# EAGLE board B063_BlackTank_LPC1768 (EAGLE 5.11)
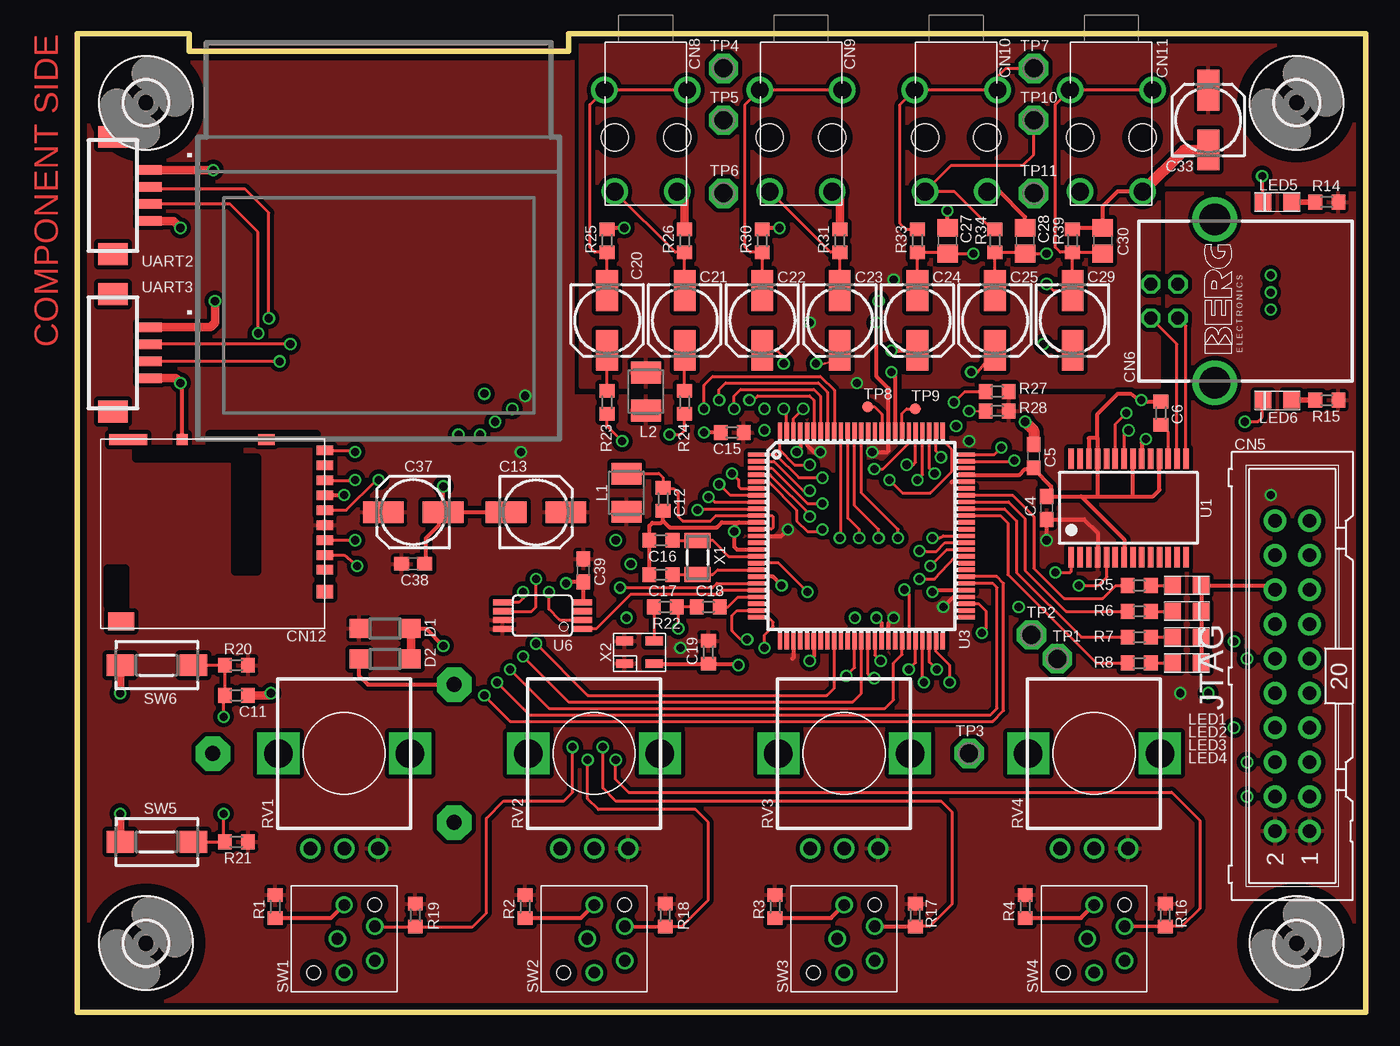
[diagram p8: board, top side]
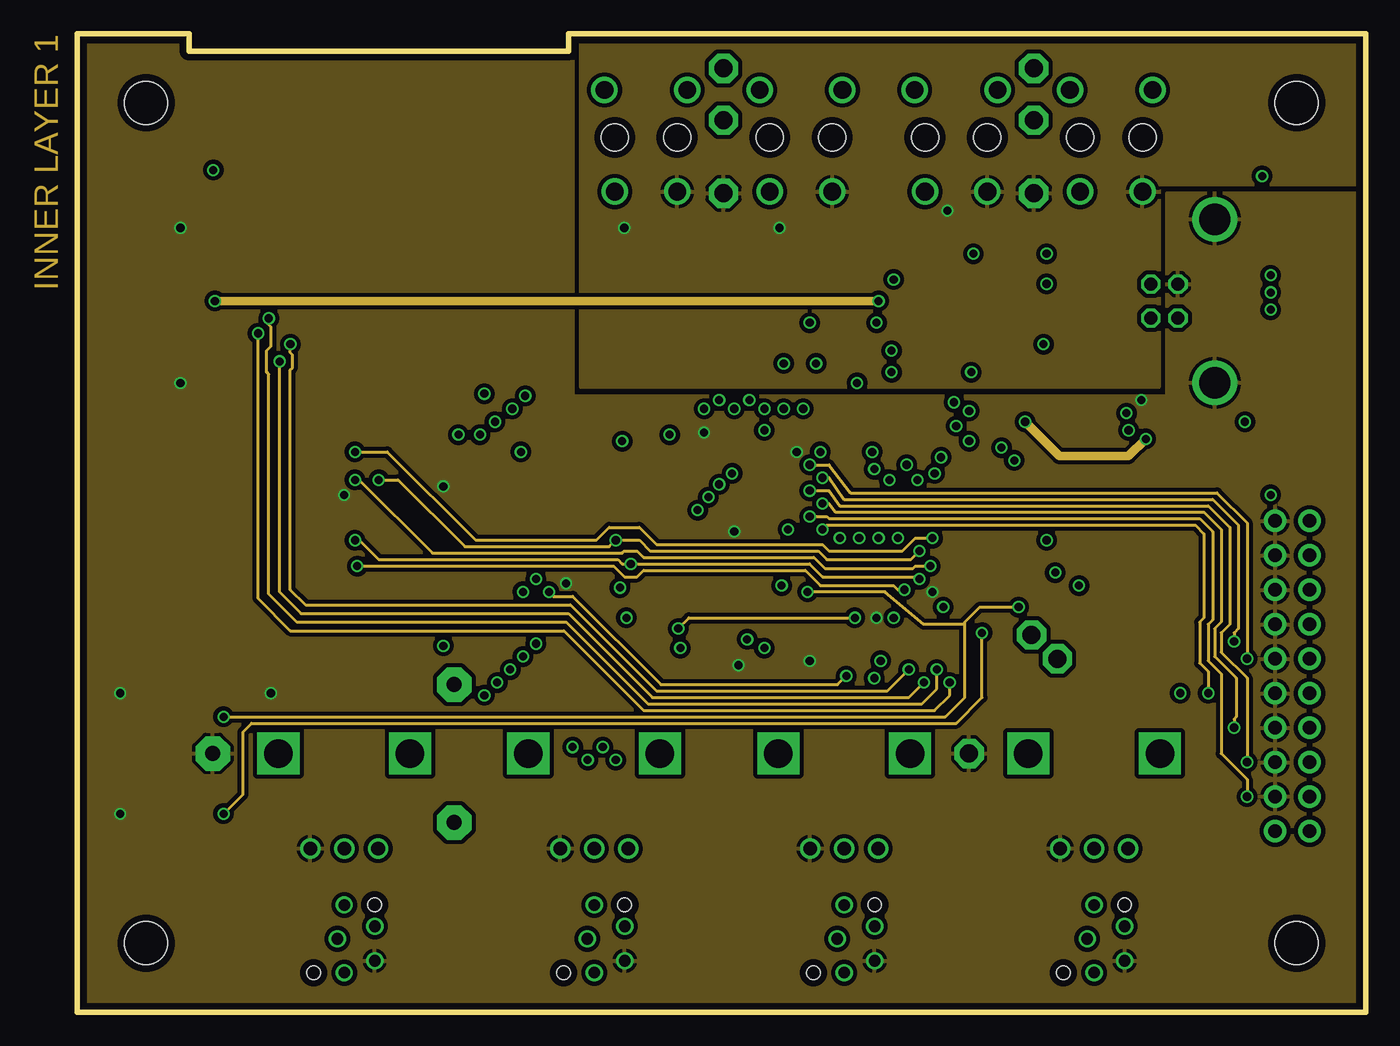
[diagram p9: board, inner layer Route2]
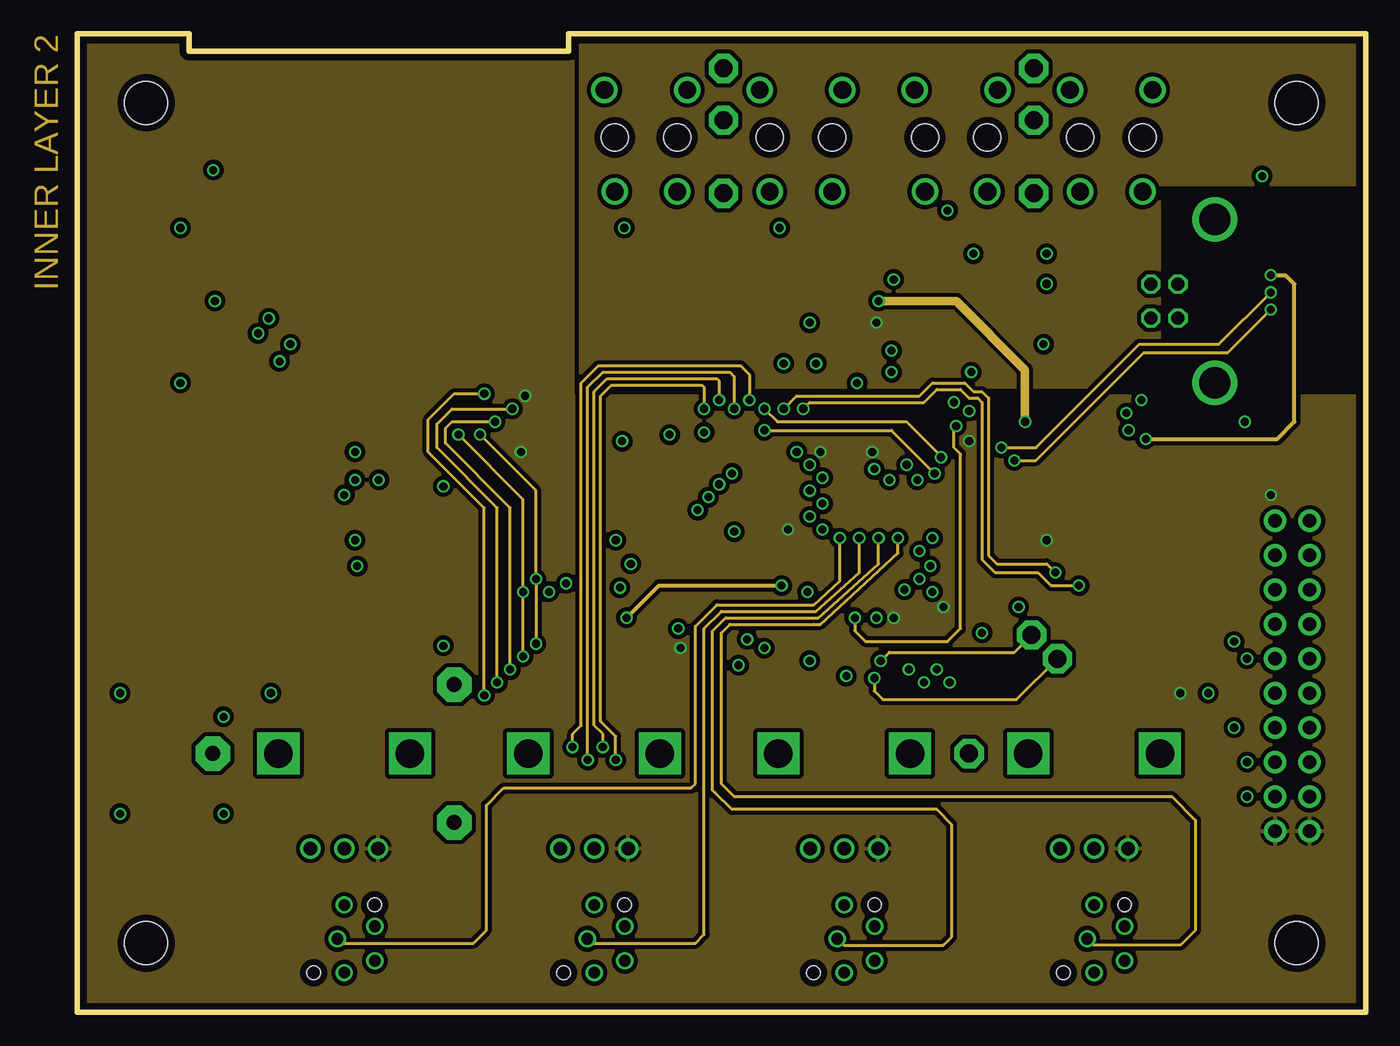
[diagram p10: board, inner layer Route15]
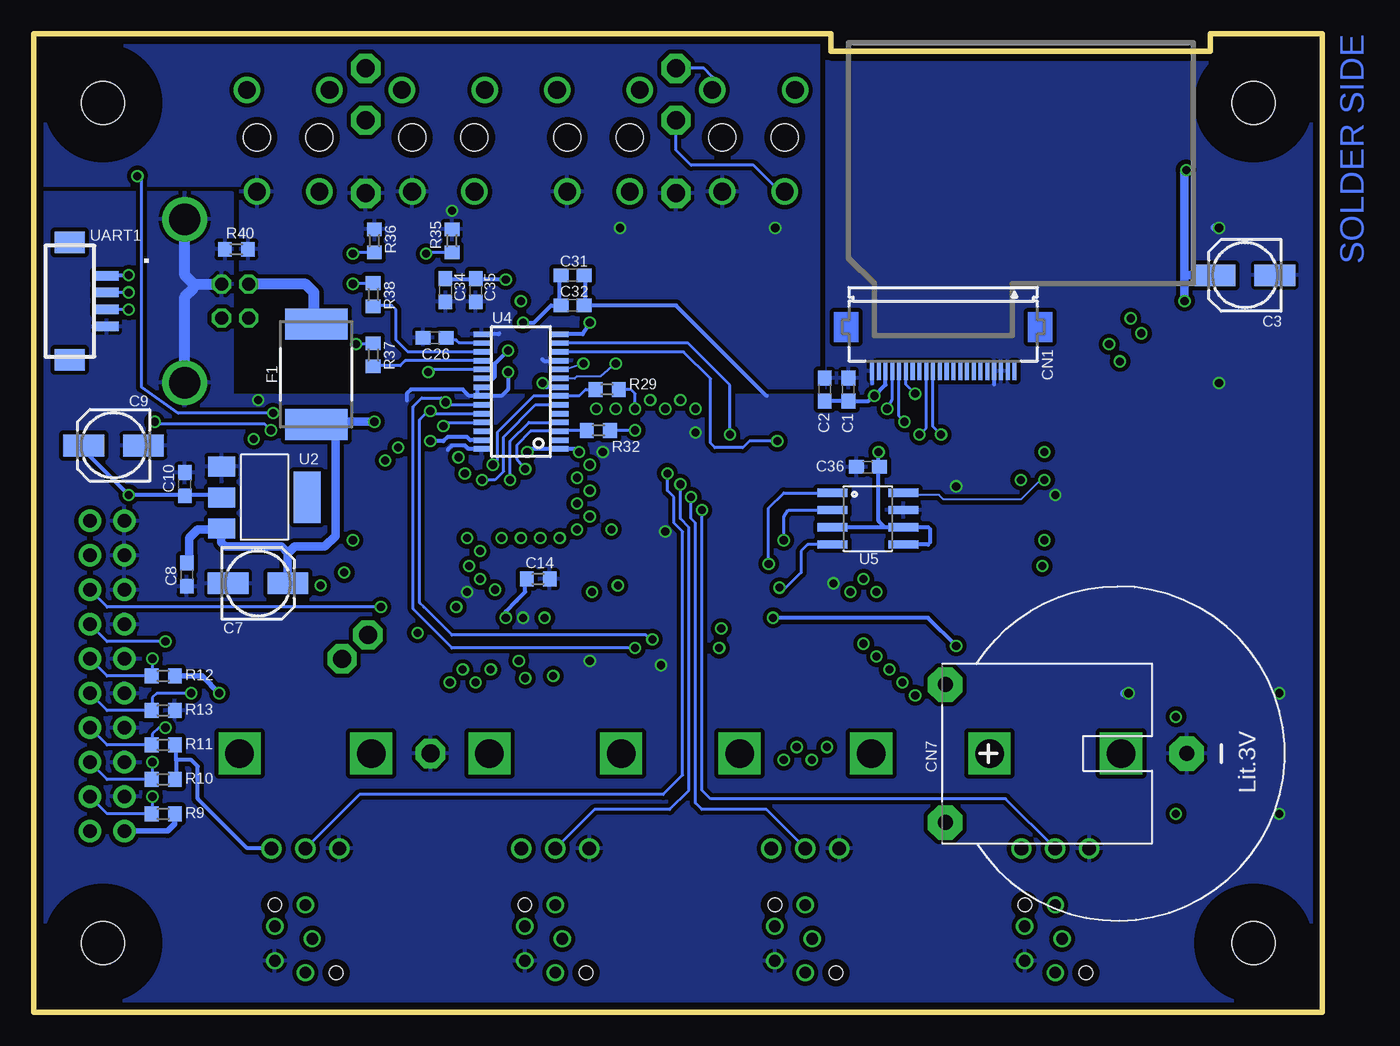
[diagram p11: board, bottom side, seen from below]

Size 94.93 x 72.07 mm. Coordinates in mm from the lower left corner, seen from the top.
Outline: 0,0 94.93,0 94.93,72.07 36.2,72.07 36.2,70.8 8.26,70.8 8.26,72.07 0,72.07 0,0
Copper layers (1+2*15+16): Top 0.018mm / dielectric 0.25mm / Route2 0.035mm / dielectric 1mm / Route15 0.035mm / dielectric 0.25mm / Bottom 0.018mm
Design rules "pban_5mil-l4 *": minimum track width 5mil, minimum drill 0.3mm, track to track 5mil, track to pad 0.229mm, pad to pad 5mil, via to via 5mil, smd to smd 5mil, copper to edge 0.5mm, drill to drill 0.5mm, minimum pad ring 0.15mm, minimum via ring 0.15mm, stop-mask expansion 4mil, vias tented up to drill 0.35mm, thermal gap 10mil
Net classes: 0 default: width 0.152 mm, drill 0.254 mm, clearance 0.152 mm; 1 PWR: width 0.305 mm, drill 0.254 mm, clearance 0.152 mm; 2 GND: width 0.305 mm, drill 0.254 mm, clearance 0.152 mm
tKeepout: area 8.9,42.1 to 35.6,70.2
bKeepout: area 8.9,51.1 to 35.6,70.2

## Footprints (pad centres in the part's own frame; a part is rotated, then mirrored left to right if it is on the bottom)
C0603 = smd 1.1 x 1: 1 -0.85,0; 2 0.85,0
153CLV-0505 = smd 3 x 1.6: + 2.2,0; - -2.2,0
0603 = smd 1 x 1.1: 1 -0.85,0; 2 0.85,0
C0805 = smd 1.3 x 1.5: 1 -0.95,0; 2 0.95,0
FH12-22S-0.5SH = smd 0.3 x 1.3: 1 -5.25,3.25; 2 -4.75,3.25; 3 -4.25,3.25; 4 -3.75,3.25; 5 -3.25,3.25; 6 -2.75,3.25; 7 -2.25,3.25; 8 -1.75,3.25; 9 -1.25,3.25; 10 -0.75,3.25; 11 -0.25,3.25; 12 0.25,3.25; 13 0.75,3.25; 14 1.25,3.25; 15 1.75,3.25; 16 2.25,3.25; 17 2.75,3.25; 18 3.25,3.25; 19 3.75,3.25; 20 4.25,3.25; 21 4.75,3.25; 22 5.25,3.25
DF13C-4P-1.25V = smd 1.6 x 2.2: M$0 4.325,-1.8; M$1 -4.325,-1.8 | smd 0.7 x 1.8: P$1 -1.875,0.9; P$2 -0.625,0.9; P$3 0.625,0.9; P$4 1.875,0.9
JTAG-20 = drill 1.016 pad 1.676 round: 1 0,0; 2 0,2.54; 3 2.54,0; 4 2.54,2.54; 5 5.08,0; 6 5.08,2.54; 7 7.62,0; 8 7.62,2.54; 9 10.16,0; 10 10.16,2.54; 11 12.7,0; 12 12.7,2.54; 13 15.24,0; 14 15.24,2.54; 15 17.78,0; 16 17.78,2.54; 17 20.32,0; 18 20.32,2.54; 19 22.86,0; 20 22.86,2.54
PN61729-S = drill 0.95 octagon: 1 1.25,4.71; 2 -1.25,4.71; 3 -1.25,2.71; 4 1.25,2.71 | drill 2.3 pad 2.9 round: S1 -6.02,0; S2 6.02,0
CR2430H = drill 1.118 pad 2.54 octagon: + 5.08,12.7; +@1 -5.08,12.7; - 0,-5.08
ST-005 = drill 1.3 round: GND -4,-2.3; L-1 3.5,3.05; L-2 3.5,-3.05; R -4,2.3 | hole 2: 0,-2.3; 0,2.3
DM3AT-SF-PEJ = smd 0.7 x 1.2: 1 2.03,7.62; 2 0.93,7.62; 3 -0.17,7.62; 4 -1.27,7.62; 5 -2.37,7.62; 6 -3.47,7.62; 7 -4.57,7.62; 8 -5.67,7.62; A -6.77,7.62 | smd 0.8 x 0.8: B -7.57,-2.88 | smd 0.8 x 1.2: PAD1 -7.57,3.32 | smd 0.8 x 2.8: PAD2 -7.57,-6.88 | smd 1.3 x 1.9: PAD3 5.83,-7.38 | smd 1 x 1.2: PAD4 3.63,7.62
SOD123 = smd 1.4 x 1.4: A 1.9,0; C -1.9,0
SMD050F = smd 2.3 x 4.6: 1 -3.7,0; 2 3.7,0
3,2 = hole 3.2: 0,0
L3230M = smd 1.6 x 2.2: 1 -1.4,0; 2 1.4,0
LED_0805 = smd 1.2 x 1.25: A 1.05,0; K -1.05,0
SK09 = drill 1 round: 1 -2.5,-7; 2 0,-7; 3 2.5,-7 | drill 2.1 square: S1 -4.85,0; S2 4.85,0
HB2 = drill 0.85 round: 1 2.25,0.92; 2 2.25,-1.62; 3 0,2.5; 4 -0.5,0; 5 0,-2.5 | hole 1: 2.25,2.5; -2.25,-2.5
DTSM-3 = smd 2 x 1.6: 1 -2.7,0; 2 2.7,0
P1-13 = drill 1.321 pad 2.159 octagon: TP 0,0
TP08R = smd 0.8 x 0.8: TP 0,0
SSOP28 = smd 0.4 x 1.5: 1 -4.225,-3.625; 2 -3.575,-3.625; 3 -2.925,-3.625; 4 -2.275,-3.625; 5 -1.625,-3.625; 6 -0.975,-3.625; 7 -0.325,-3.625; 8 0.325,-3.625; 9 0.975,-3.625; 10 1.625,-3.625; 11 2.275,-3.625; 12 2.925,-3.625; 13 3.575,-3.625; 14 4.225,-3.625; 15 4.225,3.625; 16 3.575,3.625; 17 2.925,3.625; 18 2.275,3.625; 19 1.625,3.625; 20 0.975,3.625; 21 0.325,3.625; 22 -0.325,3.625; 23 -0.975,3.625; 24 -1.625,3.625; 25 -2.275,3.625; 26 -2.925,3.625; 27 -3.575,3.625; 28 -4.225,3.625
SOT223 = smd 1.499 x 2.007: 1 -2.261,-3.15; 2 0.025,-3.15; 3 2.311,-3.15 | smd 3.81 x 2.007: 4 0,3.15
LQFP100 = smd 1.2 x 0.32: 1 -7.75,6; 2 -7.75,5.5; 3 -7.75,5; 4 -7.75,4.5; 5 -7.75,4; 6 -7.75,3.5; 7 -7.75,3; 8 -7.75,2.5; 9 -7.75,2; 10 -7.75,1.5; 11 -7.75,1; 12 -7.75,0.5; 13 -7.75,0; 14 -7.75,-0.5; 15 -7.75,-1; 16 -7.75,-1.5; 17 -7.75,-2; 18 -7.75,-2.5; 19 -7.75,-3; 20 -7.75,-3.5; 21 -7.75,-4; 22 -7.75,-4.5; 23 -7.75,-5; 24 -7.75,-5.5; 25 -7.75,-6; 51 7.75,-6; 52 7.75,-5.5; 53 7.75,-5; 54 7.75,-4.5; 55 7.75,-4; 56 7.75,-3.5; 57 7.75,-3; 58 7.75,-2.5; 59 7.75,-2; 60 7.75,-1.5; 61 7.75,-1; 62 7.75,-0.5; 63 7.75,0; 64 7.75,0.5; 65 7.75,1; 66 7.75,1.5; 67 7.75,2; 68 7.75,2.5; 69 7.75,3; 70 7.75,3.5; 71 7.75,4; 72 7.75,4.5; 73 7.75,5; 74 7.75,5.5; 75 7.75,6 | smd 0.32 x 1.2: 26 -6,-7.75; 27 -5.5,-7.75; 28 -5,-7.75; 29 -4.5,-7.75; 30 -4,-7.75; 31 -3.5,-7.75; 32 -3,-7.75; 33 -2.5,-7.75; 34 -2,-7.75; 35 -1.5,-7.75; 36 -1,-7.75; 37 -0.5,-7.75; 38 0,-7.75; 39 0.5,-7.75; 40 1,-7.75; 41 1.5,-7.75; 42 2,-7.75; 43 2.5,-7.75; 44 3,-7.75; 45 3.5,-7.75; 46 4,-7.75; 47 4.5,-7.75; 48 5,-7.75; 49 5.5,-7.75; 50 6,-7.75; 76 6,7.75; 77 5.5,7.75; 78 5,7.75; 79 4.5,7.75; 80 4,7.75; 81 3.5,7.75; 82 3,7.75; 83 2.5,7.75; 84 2,7.75; 85 1.5,7.75; 86 1,7.75; 87 0.5,7.75; 88 0,7.75; 89 -0.5,7.75; 90 -1,7.75; 91 -1.5,7.75; 92 -2,7.75; 93 -2.5,7.75; 94 -3,7.75; 95 -3.5,7.75; 96 -4,7.75; 97 -4.5,7.75; 98 -5,7.75; 99 -5.5,7.75; 100 -6,7.75
R-PDSO-G28 = smd 0.4 x 1.2: 1 -4.225,-2.9; 2 -3.575,-2.9; 3 -2.925,-2.9; 4 -2.275,-2.9; 5 -1.625,-2.9; 6 -0.975,-2.9; 7 -0.325,-2.9; 8 0.325,-2.9; 9 0.975,-2.9; 10 1.625,-2.9; 11 2.275,-2.9; 12 2.925,-2.9; 13 3.575,-2.9; 14 4.225,-2.9; 15 4.225,2.9; 16 3.575,2.9; 17 2.925,2.9; 18 2.275,2.9; 19 1.625,2.9; 20 0.975,2.9; 21 0.325,2.9; 22 -0.325,2.9; 23 -0.975,2.9; 24 -1.625,2.9; 25 -2.275,2.9; 26 -2.925,2.9; 27 -3.575,2.9; 28 -4.225,2.9
SO08 = smd 0.61 x 2.21: 1 -1.905,-2.616; 2 -0.635,-2.616; 3 0.635,-2.616; 4 1.905,-2.616; 5 1.905,2.616; 6 0.635,2.616; 7 -0.635,2.616; 8 -1.905,2.616
TSSOP8 = smd 0.45 x 1.45: 1 -0.975,-2.925; 2 -0.325,-2.925; 3 0.325,-2.925; 4 0.975,-2.925; 5 0.975,2.925; 6 0.325,2.925; 7 -0.325,2.925; 8 -0.975,2.925
FC135 = smd 1.1 x 1.9: X1 -1.25,0; X2 1.25,0
OSC3.2X.2.5 = smd 1.27 x 0.635: P$1 -1.092,-0.838; P$2 1.092,-0.838; P$3 1.092,0.838; P$4 -1.092,0.838

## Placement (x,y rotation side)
C1  0.1u  [C0603]  34.92,45.88 90 bottom
C2  0.1u  [C0603]  36.67,45.88 90 bottom
C3  10u  [153CLV-0505]  5.71,54.29 180 bottom
C4  0.1u  [C0603]  71.44,37.15 90 top
C5  0.1u  [C0603]  70.48,40.96 270 top
C6  0.1u  [0603]  79.85,44.13 270 top
C7  10u  [153CLV-0505]  78.42,31.59 0 bottom
C8  0.1u  [C0603]  83.66,32.23 270 bottom
C9  10u  [153CLV-0505]  89.06,41.75 180 bottom
C10  0.1u  [C0603]  83.82,38.89 90 bottom
C11  0.1u  [0603]  11.75,23.34 180 top
C12  0.1u  [0603]  43.18,37.78 270 top
C13  10u  [153CLV-0505]  33.81,36.83 0 top
C14  0.1u  [0603]  57.78,31.91 0 bottom
C15  0.1u  [0603]  48.26,42.7 180 top
C16  22p  [0603]  43.02,34.77 0 top
C17  22p  [0603]  43.02,32.23 0 top
C18  0.1u  [0603]  46.51,29.84 0 top
C19  0.1u  [0603]  46.51,26.51 90 top
C20  10u  [153CLV-0505]  39.05,50.96 270 top
C21  10u  [153CLV-0505]  44.77,50.96 270 top
C22  10u  [153CLV-0505]  50.48,50.96 270 top
C23  10u  [153CLV-0505]  56.2,50.96 270 top
C24  10u  [153CLV-0505]  61.91,50.96 270 top
C25  10u  [153CLV-0505]  67.63,50.96 270 top
C26  0.1u  [C0603]  65.41,49.69 180 bottom
C27  470p  [C0805]  64.14,56.83 90 top
C28  470p  [C0805]  69.85,56.83 90 top
C29  10u  [153CLV-0505]  73.34,50.96 270 top
C30  27p  [C0805]  75.56,56.83 90 top
C31  0.1u  [C0603]  55.24,54.29 0 bottom
C32  0.1u  [C0603]  55.24,52.07 0 bottom
C33  10u  [153CLV-0505]  83.34,65.72 90 top
C34  0.1u  [C0603]  64.61,53.18 270 bottom
C35  0.1u  [C0603]  62.39,53.18 270 bottom
C36  0.1u  [C0603]  33.5,40.16 180 bottom
C37  10u  [153CLV-0505]  24.77,36.83 180 top
C38  0.1u  [C0603]  24.77,33.02 0 top
C39  0.1u  [C0603]  37.31,32.54 270 top
CN1  [FH12-22S-0.5SH]  27.94,50.48 180 bottom
CN2  DF13-4P-1.25V  [DF13C-4P-1.25V]  90.49,52.39 270 bottom
CN3  [DF13C-4P-1.25V]  4.45,60.17 270 top
CN4  [DF13C-4P-1.25V]  4.45,48.58 270 top
CN5  [JTAG-20]  90.81,13.34 90 top
CN6  [PN61729-S]  83.82,52.39 90 top
CN7  CR2430H  [CR2430H]  15.08,19.05 90 bottom
CN8  [ST-005]  41.91,64.45 90 top
CN9  [ST-005]  53.34,64.45 90 top
CN10  [ST-005]  64.77,64.45 90 top
CN11  [ST-005]  76.2,64.45 90 top
CN12  [DM3AT-SF-PEJ]  10.64,34.61 270 top
D1  [SOD123]  22.7,28.26 180 top
D2  [SOD123]  22.7,26.04 180 top
F1  [SMD050F]  74.14,46.99 270 bottom
H1  [3,2]  5.08,66.99 0 top
H2  [3,2]  5.08,5.08 0 top
H3  [3,2]  89.85,5.08 0 top
H4  [3,2]  89.85,66.99 0 top
L1  22u  [L3230M]  40.48,38.26 90 top
L2  22u  [L3230M]  41.91,45.72 90 top
LED1  RED  [LED_0805]  81.76,31.43 180 top
LED2  RED  [LED_0805]  81.76,29.53 180 top
LED3  RED  [LED_0805]  81.76,27.62 180 top
LED4  RED  [LED_0805]  81.76,25.72 180 top
LED5  YELLOW  [LED_0805]  88.42,59.69 0 top
LED6  YELLOW  [LED_0805]  88.42,45.09 0 top
R1  220  [0603]  14.61,7.78 90 top
R2  220  [0603]  33.02,7.78 90 top
R3  220  [0603]  51.44,7.78 90 top
R4  220  [0603]  69.85,7.78 90 top
R5  220  [0603]  78.26,31.43 0 top
R6  220  [0603]  78.26,29.53 0 top
R7  220  [0603]  78.26,27.62 0 top
R8  220  [0603]  78.26,25.72 0 top
R9  10K  [0603]  85.41,14.61 0 bottom
R10  10K  [0603]  85.41,17.15 0 bottom
R11  10K  [0603]  85.41,19.69 0 bottom
R12  10K  [0603]  85.41,24.77 0 bottom
R13  10K  [0603]  85.41,22.23 0 bottom
R14  220  [0603]  92.08,59.69 180 top
R15  220  [0603]  92.08,45.08 180 top
R16  10K  [0603]  80.17,7.14 90 top
R17  10K  [0603]  61.75,7.14 90 top
R18  10K  [0603]  43.34,7.14 90 top
R19  10K  [0603]  24.92,7.14 90 top
R20  10K  [0603]  11.75,25.56 0 top
R21  10K  [0603]  11.75,12.54 0 top
R22  33  [0603]  43.34,29.84 180 top
R23  100  [0603]  39.05,44.93 270 top
R24  100  [0603]  44.77,44.93 270 top
R25  100K  [0603]  39.05,56.83 270 top
R26  100K  [0603]  44.77,56.83 270 top
R27  4.7K  [0603]  67.79,45.72 180 top
R28  4.7K  [0603]  67.79,44.29 180 top
R29  220  [0603]  52.7,45.88 0 bottom
R30  47K  [0603]  50.48,56.83 270 top
R31  47K  [0603]  56.2,56.83 270 top
R32  220  [0603]  53.34,42.86 0 bottom
R33  4.7K  [0603]  61.91,56.83 270 top
R34  4.7K  [0603]  67.63,56.83 270 top
R35  4.7K  [0603]  64.14,56.83 90 bottom
R36  4.7K  [0603]  69.85,56.83 90 bottom
R37  4.7K  [0603]  69.93,48.42 90 bottom
R38  10K  [0603]  69.93,52.86 90 bottom
R39  10K  [0603]  73.34,56.83 90 top
R40  0  [0603]  80.01,56.2 0 bottom
RV1  B10K  [SK09]  19.68,19.05 0 top
RV2  B10K  [SK09]  38.1,19.05 0 top
RV3  B10K  [SK09]  56.52,19.05 0 top
RV4  B10K  [SK09]  74.93,19.05 0 top
SW1  HB2-15SKP4RM  [HB2]  19.68,5.4 0 top
SW2  HB2-15SKP4RM  [HB2]  38.1,5.4 0 top
SW3  HB2-15SKP4RM  [HB2]  56.52,5.4 0 top
SW4  HB2-15SKP4RM  [HB2]  74.93,5.4 0 top
SW5  [DTSM-3]  5.87,12.54 0 top
SW6  [DTSM-3]  5.87,25.56 0 top
TP1  PTR1PAD1-13  [P1-13]  72.23,26.03 0 top
TP2  PTR1PAD1-13  [P1-13]  70.33,27.78 0 top
TP3  PTR1PAD1-13  [P1-13]  65.72,19.05 0 top
TP4  PTR1PAD1-13  [P1-13]  47.62,69.53 0 top
TP5  PTR1PAD1-13  [P1-13]  47.62,65.72 0 top
TP6  PTR1PAD1-13  [P1-13]  47.62,60.33 0 top
TP7  PTR1PAD1-13  [P1-13]  70.48,69.53 0 top
TP8  [TP08R]  58.26,44.61 270 top
TP9  [TP08R]  61.75,44.45 0 top
TP10  PTR1PAD1-13  [P1-13]  70.48,65.72 0 top
TP11  PTR1PAD1-13  [P1-13]  70.48,60.32 0 top
U1  [SSOP28]  77.47,37.15 0 top
U2  [SOT223]  77.95,37.94 270 bottom
U3  [LQFP100]  57.79,35.08 0 top
U4  [R-PDSO-G28]  59.05,45.72 90 bottom
U5  [SO08]  33.5,36.35 270 bottom
U6  23K256  [TSSOP8]  34.29,29.21 90 top
X1  32.768  [FC135]  45.72,33.5 90 top
X2  12.288  [OSC3.2X.2.5]  41.43,26.51 0 top

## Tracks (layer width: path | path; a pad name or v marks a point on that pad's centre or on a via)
12MHZ  (via drill 0.6)
  Top 0.203: C18.1 R22.1 44.29,29.74 v44.29,28.26
  Route2 0.203: v57.31,29.05 45.09,29.05 v44.29,28.26
  Route15 0.203: v64.77,43.18 64.61,43.02 64.61,41.59 65.09,41.12 65.09,28.26 64.14,27.3 58.1,27.3 57.31,28.1 v57.31,29.05 | v57.31,29.05
  Bottom 0.203: U4.25 64.5,43.45 v64.77,43.18
+3.3V  (via drill 0.6)
  Top 0.305: U3.13 51.91,35.08 v52.39,35.56 | U3.42 59.78,28.67 v60.17,29.05 | U3.54 64.56,30.58 v63.82,29.84 | U1.4 75.19,35.3 74.19,36.3 C4.1 v71.44,34.77 | v58.58,41.27 59.69,41.27 59.78,41.37 U3.84 59.78,45.94 58.9,46.83 v58.9,50.8 | U3.96 53.78,41.78 54.29,41.27 54.61,41.27 v54.77,41.27 | U3.71 64.45,39.08 64.45,39.05 | U3.28 52.78,26.11 52.7,26.04
  Top 0.406: v81.28,23.5 81.28,23.18
  Bottom 0.305: U5.6 32.23,35.72 32.7,36.2 32.7,40.11 C36.1 32.7,40.32 v32.7,41.27 | U5.6 U5.3 | U5.5 29.05,34.45 28.89,34.61 28.89,35.56 29.05,35.72 U5.6 | U2.2 81.28,38.1 83.82,38.1 C10.1 84.14,38.1 v87.95,38.1 91.44,41.59 C9.+ | 84.45,18.57 84.45,17.46 R10.2 | 84.45,18.57 84.45,19.68 R11.2 | C31.1 56.2,54.29 56.2,52.39 C32.1 56.2,52.07 56.83,52.07 58.1,50.8 v58.9,50.8 | v60.17,29.05 60.17,29.53 59.37,30.32 58.74,30.96 58.74,31.91 58.58,31.91 C14.1 | 84.45,18.57 83.34,18.57 82.87,18.1 82.87,15.72 79.22,12.06 77.63,12.06 RV4.3 | CN1.20 32.19,46.23 v33.02,45.4 33.44,45.03 C1.1 35.24,45.03 C2.1 | U4.27 62.78,42.15 63.02,42.39 64.45,42.39 64.77,42.07 v65.72,42.07 | v58.58,41.27 58.36,41.49 U4.1 54.99,41.49 v54.77,41.27
  Bottom 0.406: R9.2 84.56,13.87 85.09,13.34 CN5.2 | CN5.2 | R12.2 82.55,24.77 v81.28,23.5
  other vias: 44.45,26.83
  pour Top (isolate 0.305): 0.64,71.44 7.62,71.44 7.62,70.17 36.51,70.17 36.51,45.4 80.33,45.4 80.33,60.33 94.3,60.33 94.3,0.64 0.64,0.64
  pour Route15 (isolate 0.305): 0.64,71.44 7.62,71.44 7.62,70.17 36.51,70.17 36.51,45.4 94.3,45.4 94.3,0.64 0.64,0.64
  pour Route15 (isolate 0.305): 37.15,71.44 94.3,71.44 94.3,60.96 79.69,60.96 79.69,46.04 37.15,46.04
+5V  (via drill 0.6)
  Top 0.305: U1.20 78.44,41.93 v78.74,42.23
  Top 0.61: CN4.P$1 5.38,50.48 9.84,50.48 10.16,50.8 v10.16,52.39 10.16,51.44 | v10.03,62.04 CN3.P$1
  Top 0.813: C5.1 70.48,42.86 v69.85,43.5
  Route2 0.61: v69.85,43.5 72.39,40.96 77.47,40.96 v78.74,42.23 | v10.16,52.39 v59.05,52.39
  Route15 0.305: v78.74,42.23 88.42,42.23 89.69,43.5 89.69,53.63 89.06,54.26 87.98,54.26 v87.95,54.29
  Route15 0.61: v69.85,43.5 69.85,47.31 64.77,52.39 v59.05,52.39
  Bottom 0.305: 83.5,33.34 C8.1 | 81.28,35.56 U2.3 80.96,35.56 | F1.2 74.3,43.18 | CN2.P$1 87.98,54.26 v87.95,54.29
  Bottom 0.61: 10.13,52.42 v10.16,52.39 10.16,54.29 | v69.85,43.5 72.87,43.5 | 72.87,43.5 73.93,43.5 F1.2 | 10.16,54.29 10.16,61.91 v10.03,62.04 | 10.16,54.29 C3.+ | 83.5,33.34 83.5,34.92 82.87,35.56 81.17,35.56 U2.3 81.12,35.6 81.12,34.61 80.8,34.29 76.68,34.29 76.22,33.84 76.22,33.79 | 76.22,33.79 C7.+ | 76.22,33.79 75.72,34.29 73.5,34.29 72.71,35.08 72.71,43.34 72.87,43.5
AGND  (via drill 0.6)
  Top 0.305: R39.2 73.66,57.78 75.25,57.78 C30.2 75.56,58.9 75.56,59.37 76.68,60.48 78.47,60.48 CN11.GND | v40.32,57.78 39.05,57.78 R25.1 | v51.75,57.78 50.48,57.78 R30.1 | v64.14,59.05 C27.2 | C28.2 69.85,58.58 67.94,60.48 67.15,60.48 CN10.GND
  Top 0.61: R26.1 44.77,59.9 CN8.GND | R31.1 56.2,59.9 CN9.GND
  Top 0.813: C33.- 81.57,63.52 CN11.GND
  Bottom 0.305: U4.11 56.2,47.94 57.31,47.94 57.47,48.1 | U4.15 60.7,49.95 60.64,50.01
  pour Bottom (isolate 0.305): 37.15,71.44 94.3,71.44 94.3,60.96 79.69,60.96 79.69,60.64 79.69,46.04 37.15,46.04
  pour Route2 (isolate 0.305): 37.15,71.44 94.3,71.44 94.3,60.96 79.69,60.96 79.69,46.04 37.15,46.04
CLKSRC
  Top 0.203: R22.2 42.55,29.69 42.55,27.37 X2.P$3
FT232_3V3O
  Top 0.203: U1.17 80.39,42.74 C6.2
FT232_LED0_A
  Top 0.406: R14.2 LED5.A
FT232_LED0_C  (via drill 0.6)
  Top 0.203: U1.23 76.5,43.32 v77.31,44.13 | v87.31,61.59 87.31,59.75 LED5.K
  Bottom 0.203: v77.31,44.13 84.3,44.13 87,46.04 87,61.28 v87.31,61.59
FT232_LED1_A
  Top 0.406: R15.2 LED6.A | R15.2
FT232_LED1_C  (via drill 0.6)
  Top 0.203: U1.22 77.14,42.54 v77.47,42.86 | v86.04,43.5 87,43.5 87.31,43.81 87.31,45.02 LED6.K
  Bottom 0.203: v77.47,42.86 77.95,43.34 85.88,43.34 | 85.88,43.34 | 85.88,43.34 v86.04,43.5
GND  (via drill 0.6)
  Top 0.305: C6.1 78.53,44.98 v78.42,45.09 78.26,45.09 77.63,45.56 76.68,45.56 75.18,44.06 75.18,42.3 | U3.41 59.28,28.65 v58.9,29.05 | U3.31 54.28,26.19 v53.98,25.88 | v48.74,25.56 48.52,25.66 C19.1 X2.P$2 | U6.4 37.31,30.18 C39.2 36.14,31.69 v36.04,31.59 | C37.- 26.96,38.71 v26.99,38.73 | U1.7 77.15,33.66 77.15,34.82 73.98,38 | 82.87,27.62 82.87,29.53 | 82.87,27.62 82.87,25.72 LED4.K | 82.87,27.62 LED3.K | 82.87,29.53 82.87,31.43 | 82.87,29.53 LED2.K | C38.2 25.72,33.02 25.72,34.92 26.67,35.88 26.67,36.83 C37.- | v46.2,42.7 47.15,42.7 C15.2 | v19.68,38.1 18.41,38.1 CN12.6 | 82.87,31.43 87.95,31.43 CN5.16 | 82.87,31.43 LED1.K | U3.55 63.31,31.08 v63.02,30.96 | U3.72 69.43,39.58 69.85,40.01 70.38,40.01 C5.2 70.48,40.01 71.75,38.73 71.75,38.1 71.44,37.78 C4.2 73.98,38 | U3.97 53.28,41.54 v53.02,41.27 | U3.83 60.28,46.79 v60.01,47.15 | U1.26 74.55,42.3 75.18,42.3 | 75.18,42.3 75.19,42.12 U1.25 75.19,38 | 73.98,38 75.19,38 | 75.19,38 77.8,38 | 77.8,38 U1.21 | U1.18 79.75,38.47 79.27,38 77.8,38 | C17.1 42.17,34.13 C16.1 42.17,35.82 42.39,36.04 43.02,36.04 43.18,36.2 | 43.18,36.2 C12.2 | 48.74,36.08 47.51,36.08 47.15,35.72 43.66,35.72 43.18,36.2 | 48.74,36.08 U3.11 | U3.15 48.62,34.08 48.42,34.29 v48.42,35.4 48.42,35.77 48.74,36.08 | CN12.B 7.76,46.22 v7.62,46.35 | C37.- C13.- | C37.-
  Top 0.406: C6.1 | C6.1 79.48,44.98
  Top 0.61: CN3.P$4 7.11,58.29 v7.62,57.78 | CN4.P$4 7.27,46.7 v7.62,46.35 | SW5.1 v3.17,14.6 v3.17,14.61 | SW6.1 v3.17,23.5 | C11.1 14.13,23.34 v14.29,23.5
  Bottom 0.305: CN1.4 24.19,46.26 | CN1.22 33.19,46.34 | C31.2 54.29,54.29 54.29,52.39 C32.2 54.29,52.07 47.62,52.07 40.96,45.4 | 62.23,45.4 62.23,46.04 U4.21 | 62.23,45.4 62.87,45.4 63.34,45.88 67.15,45.88 67.47,45.56 67.47,45.09 | 62.23,45.4 U4.22 60.52,45.4 60.48,45.4 60.01,45.88 60.01,46.83 v60.01,47.15 | U4.28 62.93,41.49 63.18,41.75 64.14,41.75 64.45,41.43
  Bottom 0.61: v7.62,57.78 7.94,57.78 | v3.17,14.61 3.17,14.76 | v3.17,23.5 3.17,23.34 | v14.29,23.5 14.61,23.5
  Bottom 0.813: 83.17,53.64 CN6.4 | 83.17,53.64 83.82,54.29 CN6.S2 | 83.17,53.64 83.17,53.36 83.82,52.7 CN6.S1
  pour Bottom (isolate 0.305): 0.64,71.44 7.62,71.44 7.62,70.17 36.51,70.17 36.51,45.4 80.33,45.4 80.33,60.33 94.3,60.33 94.3,0.64 0.64,0.64
  pour Route2 (isolate 0.305): 0.64,71.44 7.62,71.44 7.62,70.17 36.51,70.17 36.51,45.4 80.33,45.4 80.33,60.33 94.3,60.33 94.3,0.64 0.64,0.64
I2C1_SCL  (via drill 0.6)
  Top 0.152: v65.72,44.29 R28.2
  Top 0.203: v49.37,27.46 48.9,27.46 48.26,28.1 48.26,29.21 48.63,29.58 U3.24
  Bottom 0.203: v49.37,27.46 49.85,27.78 64.14,27.78 66.2,29.84 66.52,30.16 66.52,43.66 65.88,44.29 v65.72,44.29 65.56,44.29 65.37,44.09 U4.24
I2C1_SDA  (via drill 0.6)
  Top 0.203: R27.2 65.41,45.72 v64.61,44.93 | U3.25 50.93,29.08 51.28,28.73 51.28,28.42 50.64,27.78 v50.64,26.83
  Bottom 0.203: v50.64,26.83 50.8,26.83 64.14,26.83 66.99,29.69 66.99,44.61 66.36,45.24 64.93,45.24 v64.61,44.93 64.43,44.74 U4.23
I2S_RX_CLK  (via drill 0.6)
  Top 0.203: v58.74,40.01 59.37,40.01 61.28,41.92 U3.81
  Bottom 0.203: R32.1 56.16,42.86 U4.3 58.33,42.8 59.37,41.75 59.37,40.8 v58.74,40.01
I2S_RX_MCLK
  Top 0.203: U3.82 60.78,44.12 61.12,44.45 TP9.TP
I2S_RX_SDA  (via drill 0.6)
  Top 0.203: U3.79 62.28,39.58 v61.91,39.21
  Bottom 0.203: U4.6 57.97,44.74 60.33,42.39 60.33,39.85 60.96,39.21 v61.91,39.21 | v61.91,39.21
I2S_RX_WS  (via drill 0.6)
  Top 0.203: v61.12,40.32 61.59,40.32 61.78,40.51 U3.80
  Bottom 0.203: R29.1 54.29,45.88 54.77,45.4 56.16,45.4 U4.7 58.11,45.4 60.8,42.7 60.8,40.64 v61.12,40.32
I2S_TX_CLK  (via drill 0.6)
  Top 0.203: U3.78 62.78,40.09 v63.18,39.69
  Route15 0.203: v63.18,39.69 | v63.18,39.69 60.01,42.86 v50.64,42.86
  Bottom 0.203: v50.64,42.86 R32.2 | R32.2
I2S_TX_MCLK
  Top 0.203: U3.85 59.28,44.06 58.74,44.61 TP8.TP
I2S_TX_SDA  (via drill 0.6)
  Top 0.203: U3.76 63.78,42.1 64.45,41.43 64.45,39.85 62.87,38.26 60.8,38.26 v59.85,39.21
  Bottom 0.203: U4.4 58.47,43.45 59.85,42.07 v59.85,39.21 | v59.85,39.21
I2S_TX_WS  (via drill 0.6)
  Top 0.203: U3.77 63.28,41.33 63.66,40.96 v63.66,40.88
  Route15 0.203: v63.66,40.88 63.66,40.96 61.12,43.5 51.59,43.5 v50.64,44.45
  Bottom 0.203: v50.64,44.45 50.64,45.56 50.96,45.88 R29.2
IC6_RTC1
  Top 0.203: C16.2 43.89,34.75 X1.X2 45.74,34.77 46.83,34.77 48.01,33.58 U3.16
IC6_RTC2
  Top 0.203: U3.18 47.19,32.58 46.85,32.25 X1.X1 43.89,32.25 C17.2
ISP_ENT  (via drill 0.6)
  Top 0.203: SW5.2 R21.1 10.79,12.64 v10.79,14.61 | U3.53 66.44,30.08 66.99,29.53 66.99,28.26 v66.67,27.94
  Route2 0.203: v66.67,27.94 66.67,23.18 64.77,21.27 12.86,21.27 12.22,20.64 12.22,16.03 v10.79,14.61
L1A
  Top 0.203: LED1.A R5.2
L2A
  Top 0.203: R6.2 LED2.A
L3A
  Top 0.203: LED3.A R7.2
L4A
  Top 0.203: R8.2 LED4.A
LED1
  Top 0.203: R5.1 76.52,31.43 75.56,30.48 72.71,30.48 70.48,32.7 70.48,36.51 68.91,38.08 U3.69
LED2
  Top 0.203: R6.1 72.87,29.53 69.85,32.54 69.85,36.35 68.62,37.58 U3.68
LED3
  Top 0.203: R7.1 73.98,27.62 69.22,32.38 69.22,36.2 68.33,37.08 U3.67
LED4
  Top 0.203: R8.1 75.09,25.72 68.58,32.23 68.58,36.04 68.03,36.58 U3.66
LICN_L
  Top 0.203: CN10.L-2 CN10.L-1 60.64,66.88 60.64,58.1 61.06,57.68 R33.1 | CN10.L-2 68.41,67.95 67.79,67.94 CN10.L-2 | TP7.TP 68.42,69.53 67.79,68.9 67.79,67.99 CN10.L-2
LICN_R
  Top 0.203: R34.1 67.41,57.68 64.61,60.48 62.5,60.48 CN10.R 64.41,62.39 69.69,62.39 70.48,63.18 TP10.TP
LICR_L  (via drill 0.6)
  Top 0.203: C24.- 61.91,52.84 R33.2 64.03,55.98 C27.1 v66.04,55.88
  Bottom 0.203: R35.1 65.94,55.98 v66.04,55.88
LICR_R  (via drill 0.6)
  Top 0.203: C25.- 67.63,52.84 R34.2 69.75,55.98 C28.1 v71.44,55.88
  Bottom 0.203: R36.1 71.33,55.98 v71.44,55.88
LOCN_L
  Top 0.203: C20.- R25.2 38.16,55.98 37.78,56.36 37.78,66.88 CN8.L-1 CN8.L-2
  Bottom 0.203: CN8.L-2 44.96,68.93 45.56,69.53 TP4.TP
LOCN_R
  Top 0.203: C21.- R26.2 44.08,55.98 CN8.R
  Bottom 0.203: CN8.R 39.97,60.45 41.91,62.39 46.51,62.39 47.62,63.5 TP5.TP | TP5.TP
LORC_L
  Top 0.203: R23.1 C20.+
LORC_R
  Top 0.203: R24.1 C21.+
MCRC_L  (via drill 0.6)
  Top 0.203: C29.+ 72.21,48.76 71.75,49.21 v71.2,49.21
  Bottom 0.152: R37.2 70.17,49.21
  Bottom 0.203: 70.17,49.21 v71.2,49.21
MICN_L  (via drill 0.6)
  Top 0.203: CN11.L-2 CN11.L-1 72.07,66.88 72.07,56.36 72.45,55.98 R39.1 | R39.1 C29.- 71.94,53.16 v71.44,53.66 | R39.1 75.47,55.98 C30.1
  Bottom 0.203: v71.44,53.66 70.06,53.66 R38.2
MPU_RXD0  (via drill 0.6)
  Top 0.203: U3.99 52.28,44.19 v52.07,44.45 | U1.1 73.25,32.45 73.18,32.38 v72.07,32.38
  Route15 0.203: v52.07,44.45 53.02,45.4 62.07,45.4 63.02,46.35 65.41,46.35 66.04,45.72 66.67,45.72 67.15,45.24 67.15,45.09 67.15,33.66 67.79,33.02 71.44,33.02 v72.07,32.38
MPU_RXD1  (via drill 0.6)
  Top 0.203: U3.74 68.84,40.58 v69.06,40.64
  Route15 0.203: v69.06,40.64 70.64,40.64 78.58,48.58 84.77,48.58 v87.95,51.75
  Bottom 0.203: v87.95,51.75 89.58,51.75 CN2.P$3
MPU_RXD2  (via drill 0.6)
  Top 0.203: v64.29,24.29 64.29,25.56 63.28,26.57 U3.49 | v13.34,50.01 13.34,57.47 11.27,59.53 CN3.P$3
  Route2 0.203: v64.29,24.29 64.29,23.34 63.18,22.23 41.75,22.23 35.88,28.1 15.72,28.1 13.34,30.48 v13.34,50.01
MPU_RXD3  (via drill 0.6)
  Top 0.203: U3.47 62.28,24.5 v62.39,24.29 | v14.92,47.94 CN4.P$3
  Route2 0.203: v62.39,24.29 61.28,23.18 42.39,23.18 36.2,29.37 16.51,29.37 14.92,30.96 v14.92,47.94
MPU_TXD0  (via drill 0.6)
  Top 0.203: U3.98 52.78,43.74 v53.5,44.45 | v73.82,31.43 75.25,31.43 75.88,32.07 75.88,33.48 U1.5
  Route15 0.203: v53.5,44.45 53.98,44.93 62.39,44.93 63.34,45.88 65.09,45.88 65.72,45.24 66.36,45.24 66.67,44.93 66.67,33.34 67.63,32.38 70.8,32.38 71.75,31.43 v73.82,31.43
MPU_TXD1  (via drill 0.6)
  Top 0.203: U3.75 67.59,41.08 v68.1,41.59
  Route15 0.203: v68.1,41.59 70.64,41.59 78.26,49.21 84.14,49.21 v87.95,53.02
  Bottom 0.203: v87.95,53.02 89.58,53.02 CN2.P$2
MPU_TXD2  (via drill 0.6)
  Top 0.203: U3.48 62.78,25.8 v63.34,25.24 | v14.13,51.12 14.13,58.9 12.38,60.64 5.49,60.64 CN3.P$2
  Route2 0.203: v63.34,25.24 63.34,23.81 62.23,22.7 42.07,22.7 36.04,28.73 16.19,28.73 14.13,30.8 14.13,46.99 13.97,47.15 13.97,48.74 14.29,49.05 14.29,50.48 14.13,50.64 v14.13,51.12
MPU_TXD3  (via drill 0.6)
  Top 0.203: U3.46 61.78,25.75 v61.28,25.24 | v15.72,49.21 5.36,49.21 CN4.P$2
  Route2 0.203: v61.28,25.24 59.69,23.65 42.7,23.65 36.35,30 16.83,30 15.72,31.11 15.72,47.31 15.88,47.47 15.88,48.42 15.72,48.58 v15.72,49.21
N$3
  Top 0.203: C18.2 47.94,29.84 48.68,30.58 U3.22
OLED_DC  (via drill 0.6)
  Top 0.203: U3.57 67.77,32.08 68.26,31.59 68.26,22.23 67.47,21.43 31.91,21.43 v30,23.34
  Route15 0.203: v30,23.34 30,37.15 25.88,41.27 25.88,43.66 27.78,45.56 v30,45.56
  Bottom 0.203: CN1.17 30.69,46.25 v30,45.56
OLED_RST  (via drill 0.6)
  Top 0.203: U3.56 65.53,31.59 67.47,31.59 67.79,31.27 67.79,22.38 67.31,21.91 33.34,21.91 v30.96,24.29
  Route15 0.203: v30.96,24.29 30.96,37.15 26.51,41.59 26.51,43.34 27.62,44.45 v32.07,44.45
  Bottom 0.203: CN1.19 31.69,45.15 v32.07,44.45
POCN_L
  Top 0.203: C22.- R30.2 49.59,55.98 49.21,56.36 49.21,66.88 CN9.L-1 CN9.L-2
POCN_R
  Top 0.203: C23.- R31.2 55.51,55.98 CN9.R
S1L_RED  (via drill 0.6)
  Top 0.203: U3.91 56.28,35.01 v56.2,34.92
  Route15 0.203: 31.43,16.51 45.24,16.51 45.56,16.83 45.56,28.42 47.15,30 54.29,30 56.2,31.75 v56.2,34.92 | 31.43,16.51 | 31.43,16.51 30.16,15.24 30.16,6.03 29.21,5.08 19.5,5.08 SW1.4
S2L_RED  (via drill 0.6)
  Top 0.203: U3.90 56.78,36.4 57.63,35.56 v57.63,34.92
  Route15 0.203: SW2.4 37.92,5.08 45.56,5.08 46.2,5.71 46.2,28.26 47.47,29.53 54.45,29.53 57.63,32.38 v57.63,34.92
S3L_RED  (via drill 0.6)
  Top 0.203: U3.89 57.28,37.33 59.05,35.56 v59.05,34.92
  Route15 0.203: SW3.4 56.49,4.92 63.82,4.92 64.45,5.56 64.45,13.81 63.34,14.92 48.26,14.92 47.01,16.17 46.83,16.33 46.83,28.1 47.78,29.05 54.61,29.05 59.05,33.02 v59.05,34.92
S4L_RED  (via drill 0.6)
  Top 0.203: U3.88 57.78,38.26 60.48,35.56 60.48,35.4 v60.48,34.92
  Route15 0.203: SW4.4 74.91,4.92 81.28,4.92 82.39,6.03 82.39,14.13 80.64,15.88 48.42,15.88 47.47,16.83 47.47,27.94 48.1,28.57 54.29,28.57 54.77,28.57 60.48,33.81 v60.48,34.92
SD_DET  (via drill 0.6)
  Top 0.203: CN12.A 20.38,41.38 v20.48,41.27 | v63.02,34.92 63.5,34.92 63.82,35.08 U3.63
  Route2 0.203: v20.48,41.27 22.86,41.27 29.37,34.77 38.26,34.77 39.21,35.72 41.43,35.72 42.7,34.45 54.93,34.45 55.4,33.97 60.8,33.97 61.75,34.92 v63.02,34.92
SLA1
  Top 0.305: R1.1 18.72,6.93 SW1.3
SLA2
  Top 0.305: R2.1 37.13,6.93 SW2.3
SLA3
  Top 0.305: R3.1 55.55,6.93 SW3.3
SLA4
  Top 0.305: R4.1 73.96,6.93 SW4.3
SPI1_CS_ROM  (via drill 0.6)
  Top 0.203: U3.20 47.14,31.58 46.83,31.27 40.16,31.27 v40.01,31.27
  Bottom 0.203: U5.4 37.94,34.45 38.42,33.97 38.42,32.38 39.53,31.27 | 39.53,31.27 | 39.53,31.27 v40.01,31.27
SPI1_CS_SDC  (via drill 0.6)
  Top 0.203: CN12.2 19.66,33.68 v20.64,32.86 | U3.45 61.28,30.79 v60.96,31.11
  Route2 0.203: v20.64,32.86 39.53,32.86 40.32,32.07 41.27,32.07 41.75,32.54 53.66,32.54 54.77,31.43 55.09,31.43 60.17,31.43 60.48,31.11 v60.96,31.11
SPI1_MISO  (via drill 0.6)
  Top 0.203: CN12.7 20.45,39.18 v20.48,39.21 | U3.61 64.09,34.08 v62.87,32.86
  Route2 0.203: v20.48,39.21 20.8,39.21 26.19,33.81 40.16,33.81 40.32,33.97 41.27,33.97 41.75,33.5 54.29,33.5 55.09,32.7 61.59,32.7 61.75,32.86 v62.87,32.86
  Bottom 0.152: U5.8 30.8,38.1 28.26,38.1 27.94,37.78 22.23,37.78 20.8,39.21 v20.48,39.21
SPI1_MOSI  (via drill 0.6)
  Top 0.203: CN12.3 20.47,34.78 v20.48,34.77 | v62.07,31.91 63.18,31.91 64.7,33.58 U3.60
  Route2 0.203: v20.48,34.77 20.8,34.77 22.23,33.34 39.85,33.34 40.16,33.02 v40.8,33.02 53.98,33.02 54.93,32.07 61.91,32.07 v62.07,31.91 | v62.07,31.91
  Bottom 0.203: U5.1 39.69,38.26 40.8,37.15 v40.8,33.02
SPI1_SCLK  (via drill 0.6)
  Top 0.203: v22.23,39.21 22.07,39.21 19.83,36.98 CN12.5 | v62.07,33.97 62.52,33.95 63.32,33.95 63.95,34.58 U3.62
  Route2 0.203: v22.23,39.21 23.65,39.21 28.57,34.29 39.21,34.29 v39.69,34.77 41.43,34.77 42.23,33.97 54.61,33.97 55.24,33.34 61.44,33.34 v62.07,33.97 | v62.07,33.97
  Bottom 0.203: U5.2 39.37,36.99 39.69,36.51 v39.69,34.77
SPI2_CS_OLED  (via drill 0.6)
  Top 0.203: v31.91,25.24 34.77,22.38 59.53,22.38 60.17,23.02 60.17,25.72 60.78,26.34 U3.44
  Route15 0.203: v31.91,25.24 31.91,37.15 27.15,41.91 27.15,43.02 27.62,43.5 v30.8,43.5
  Bottom 0.203: CN1.18 31.19,43.9 v30.8,43.5
SPI2_CS_RAM
  Top 0.203: U3.21 47.59,31.08 47.31,30.8 40.8,30.8 38.26,28.26 37.55,28.26 U6.1
SPI2_MISO  (via drill 0.6)
  Top 0.203: U3.37 57.28,25.38 v56.67,24.77 | v34.77,30.96 34.77,29.69 35.56,28.89 36.57,28.89 U6.2
  Route2 0.203: v56.67,24.77 56.04,24.13 55.56,24.13 43.02,24.13 36.51,30.64 35.08,30.64 v34.77,30.96 | v34.77,30.96
SPI2_MOSI  (via drill 0.6)
  Top 0.203: U3.38 57.78,23.5 57.15,22.86 36.2,22.86 v32.86,26.19 | U6.5 32.57,30.18 32.86,30.48 v32.86,30.96
  Route15 0.203: v32.86,26.19 v32.86,30.96 32.86,37.78 v28.1,42.55
  Bottom 0.203: CN1.13 28.69,43.14 v28.1,42.55
SPI2_SCLK  (via drill 0.6)
  Top 0.203: v33.81,27.15 37.62,23.34 55.24,23.34 55.78,23.88 U3.34 | U6.6 33.49,29.54 33.81,29.84 v33.81,31.91
  Route15 0.203: v29.69,42.55 33.81,38.42 v33.81,31.91 v33.81,27.15
  Bottom 0.203: CN1.14 29.19,43.04 v29.69,42.55
SW1  (via drill 0.6)
  Top 0.203: SW1.1 21.96,6.29 R19.1 29.15,6.29 30.16,7.3 30.16,14.29 31.43,15.56 35.88,15.56 36.51,16.19 v36.51,19.53 | U3.95 54.28,45.09 53.98,45.4 50.16,45.4 49.85,45.09 v49.53,45.09
  Route15 0.203: v49.53,45.09 49.53,46.99 48.9,47.62 38.42,47.62 37.15,46.35 37.15,21.11 36.51,20.48 v36.51,19.53
SW2  (via drill 0.6)
  Top 0.203: R18.1 40.37,6.29 SW2.1 44.58,6.32 46.51,8.26 46.51,13.97 45.56,14.92 38.42,14.92 37.62,15.72 v37.62,18.57 | U3.94 54.78,45.39 54.29,45.88 48.9,45.88 | v48.42,44.45 48.42,45.4 48.9,45.88 | 48.9,45.88
  Route15 0.203: v48.42,44.45 48.42,46.83 48.1,47.15 38.73,47.15 37.62,46.04 v37.62,18.57
SW3  (via drill 0.6)
  Top 0.203: R17.1 58.79,6.29 SW3.1 62.83,6.32 64.45,7.94 64.45,14.76 63.66,15.56 39.69,15.56 38.73,16.51 v38.73,19.53 | U3.93 55.28,45.68 54.61,46.35 47.78,46.35 47.31,45.88 v47.31,45.09
  Route15 0.203: v47.31,45.09 47.31,46.51 47.15,46.67 39.05,46.67 38.1,45.72 38.1,21.11 38.73,20.48 v38.73,19.53
SW4  (via drill 0.6)
  Top 0.203: R16.1 80.14,6.32 SW4.1 81.41,6.32 82.71,7.62 82.71,14.13 80.64,16.19 40.64,16.19 39.69,17.14 v39.69,18.57 | U3.92 55.78,45.81 54.77,46.83 46.83,46.83 | v46.2,44.45 46.2,46.2 46.83,46.83 | 46.83,46.83
  Route15 0.203: v46.2,44.45 46.2,46.04 46.04,46.2 39.37,46.2 38.58,45.4 38.58,21.43 39.69,20.32 v39.69,18.57
TGT_NRESET  (via drill 0.6)
  Top 0.203: SW6.2 R20.1 C11.2 10.79,23.23 v10.79,21.75 | U3.17 51.69,33.08 v53.82,30.96
  Route2 0.203: v53.82,30.96 59.53,30.96 62.39,28.57 65.41,28.57 | 65.41,28.57 65.41,23.18 63.98,21.75 v10.79,21.75 | 65.41,28.57 65.41,28.73 66.52,29.84 v69.37,29.84
  Bottom 0.203: v69.37,29.84 89.53,29.84 CN5.15
TGT_RTCK  (via drill 0.6)
  Top 0.203: U3.100 51.78,41.4 52.86,40.32 v53.98,40.32
  Route2 0.203: v53.98,40.32 55.4,40.32 56.99,38.26 83.98,38.26 86.2,36.04 v86.2,26.04
  Bottom 0.203: CN5.11 89.53,24.77 R12.1 86.2,24.82 v86.2,26.04
TGT_TCK  (via drill 0.6)
  Top 0.203: U3.5 50.93,39.08 | v54.93,35.56 54.77,35.4 53.82,35.4 53.02,36.2 53.02,36.99 50.93,39.08 | 50.93,39.08
  Route2 0.203: v54.93,35.56 55.24,35.88 82.39,35.88 83.03,35.24 83.03,29.05 82.71,28.73 82.71,25.72 83.34,25.08 v83.34,23.5
  Bottom 0.203: CN5.9 89.53,22.23 R13.1 86.2,22.28 86.2,23.18 85.88,23.5 v83.34,23.5
TGT_TDI  (via drill 0.6)
  Top 0.203: U3.2 51.33,40.58 53.5,38.42 v53.98,38.42
  Route2 0.203: v53.98,38.42 55.4,38.42 56.2,37.31 83.34,37.31 84.93,35.72 84.93,28.57 84.3,27.94 84.3,26.51 86.2,24.61 v86.2,18.41
  Bottom 0.203: CN5.5 89.53,17.14 R10.1 86.2,17.2 v86.2,18.41 | v86.2,18.41
TGT_TDO  (via drill 0.6)
  Top 0.203: U3.1 51.47,41.08 53.18,39.37 v54.93,39.37
  Route2 0.203: v54.93,39.37 55.4,39.37 56.52,37.78 83.66,37.78 85.57,35.88 85.57,28.26 85.25,27.94 v85.25,27.3
  Bottom 0.203: CN5.13 89.53,27.3 v85.25,27.3
TGT_TMS  (via drill 0.6)
  Top 0.203: U3.3 51.2,40.08 53.82,37.47 v54.93,37.47
  Route2 0.203: v54.93,37.47 55.4,37.47 55.88,36.83 83.03,36.83 84.3,35.56 84.3,28.73 83.82,28.26 83.82,26.19 85.41,24.61 85.41,21.75 85.25,21.59 v85.25,20.95
  Bottom 0.203: CN5.7 89.53,19.68 R11.1 86.2,19.74 86.2,20.48 85.72,20.95 v85.25,20.95
TGT_TRST  (via drill 0.6)
  Top 0.203: U3.4 51.06,39.58 54.13,36.51 v53.98,36.51
  Route2 0.203: v53.98,36.51 55.24,36.51 55.4,36.35 82.71,36.35 83.66,35.4 83.66,28.89 83.34,28.57 83.34,25.88 84.3,24.92 84.3,19.05 86.2,17.14 v86.2,15.88
  Bottom 0.203: CN5.3 89.53,14.61 R9.1 86.2,14.66 v86.2,15.88
TLV320_LHPOUT  (via drill 0.6)
  Top 0.203: C22.+ 51.57,48.76 52.07,48.26 v52.07,47.78
  Bottom 0.152: v52.07,47.78 53.18,46.83 54.93,46.83 55.09,46.67 U4.9
TLV320_LLINEIN  (via drill 0.6)
  Top 0.305: v60.01,48.74 61.89,48.74 C24.+
  Bottom 0.152: U4.20 62.23,46.67
  Bottom 0.305: 62.23,46.67 61.12,46.67 60.96,46.83 60.96,47.78 v60.01,48.74
TLV320_LOUT  (via drill 0.6)
  Top 0.203: R23.2 39.05,43.18 v40.16,42.07
  Bottom 0.203: U4.12 47.06,48.65 45.09,46.67 45.09,41.91 44.77,41.59 42.7,41.59 42.23,42.07 v40.16,42.07
TLV320_MICBIAS
  Bottom 0.203: U4.17 67.38,48.65 68.26,49.53 68.26,51.75 68.58,52.07 69.95,52.07 R38.1
TLV320_MICIN
  Bottom 0.203: U4.18 67.58,47.99 67.94,47.62 69.95,47.62 R37.1
TLV320_RHPOUT  (via drill 0.6)
  Top 0.152: v54.45,47.78 55.09,47.78 56.2,48.26 C23.+
  Bottom 0.152: v54.45,47.78 55.88,47.31 U4.10
TLV320_RLINEIN  (via drill 0.6)
  Top 0.203: v65.88,47.15 66.33,47.15 C25.+
  Bottom 0.203: U4.19 65.69,47.34 v65.88,47.15
TLV320_ROUT  (via drill 0.6)
  Top 0.203: R24.2 44.77,42.86 44.45,42.55 v43.66,42.55
  Bottom 0.203: U4.13 46.76,49.3 43.66,46.2 v43.66,42.55
TLV320_VMID
  Bottom 0.203: U4.16 63.58,49.3 63.82,49.53 64.4,49.53 C26.1
TP_P1.25  (via drill 0.6)
  Top 0.203: U3.39 58.28,24.9 v58.74,24.61
  Route15 0.203: TP1.TP | v58.74,24.61 58.74,23.65 59.37,23.02 69.22,23.02 TP1.TP
TP_P1.26  (via drill 0.6)
  Top 0.203: U3.40 58.78,26.3 v59.21,25.88
  Route15 0.203: v59.21,25.88 59.85,26.51 69.06,26.51 TP2.TP
USB_DM
  Top 0.203: U1.16 81.05,49.2 CN6.2
USB_DP
  Top 0.203: U1.15 81.69,50.55 CN6.3
VBAT  (via drill 0.6)
  Top 0.305: U3.19 51.26,32.08 v51.91,31.43 | v26.99,26.99 25.72,28.26 25.55,28.26 D1.C
  Top 0.61: D2.C D1.C
  Route15 0.305: v51.91,31.43 42.86,31.43 v40.48,29.05
  Bottom 0.305: v40.48,29.05 29.05,29.05 v26.99,26.99
VBAT_IN
  Top 0.305: D2.A 20.8,24.76 21.43,24.13 CN7.+
VCC
  Bottom 0.813: CN6.1 74.91,53.64 74.3,53.02 74.3,51.17 F1.1
VDD  (via drill 0.6)
  Top 0.305: v53.98,50.8 53.66,50.8
  Bottom 0.305: v57.47,46.35 57.15,46.04 56.2,46.04 U4.8 | C34.1 64.45,53.98 62.55,53.98 C35.1 62.23,53.98 v60.17,53.98 | U4.14 54.51,49.95 v53.98,50.8
  pour Top (isolate 0.305): 37.15,71.44 94.3,71.44 94.3,60.96 79.69,60.96 79.69,60.64 79.69,46.04 37.15,46.04
VR1  (via drill 0.6)
  Top 0.203: U3.9 45.81,37.08 v45.72,36.99
  Bottom 0.203: v45.72,36.99 45.72,16.35 45.09,15.72 23.35,15.72 RV1.2
VR2  (via drill 0.6)
  Top 0.203: U3.8 46.95,37.58 v46.51,37.94
  Bottom 0.203: v46.51,37.94 46.51,36.35 46.2,36.04 46.2,15.4 45.72,14.92 40.97,14.92 RV2.2
VR3  (via drill 0.6)
  Top 0.203: U3.7 48.12,38.08 v47.31,38.89
  Bottom 0.203: v47.31,38.89 47.31,36.35 46.67,35.72 46.67,16.35 48.1,14.92 53.64,14.92 RV3.2
VR4  (via drill 0.6)
  Top 0.203: U3.6 48.89,38.58 48.74,38.73 48.74,39.21 v48.26,39.69
  Bottom 0.203: v48.26,39.69 48.26,38.42 47.78,37.94 47.78,36.04 47.15,35.4 47.15,17.46 48.58,16.03 70.95,16.03 RV4.2
VREFP
  Top 0.203: U3.12 51.14,35.58 51.28,35.72 51.28,36.51 51.2,36.58 U3.10 47.06,36.58 46.67,36.2 44.61,36.2 44.29,36.51 44.29,38.26 43.97,38.58 43.24,38.58 C12.1 43.18,39.37 42.86,39.69 40.51,39.69 L1.2

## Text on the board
Top: COMPONENT SIDE
Route2: INNER LAYER 1
Route15: INNER LAYER 2
Bottom: SOLDER SIDE
tPlace: UART2 | UART3
bPlace: UART1
bValues: Black Tank LPC1769 REV A | Copyright(C) 2011 @shintamainjp | Special thanks to Kaneko-san. | Special thanks to Horie-san.
tDocu: OLED | 96x64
